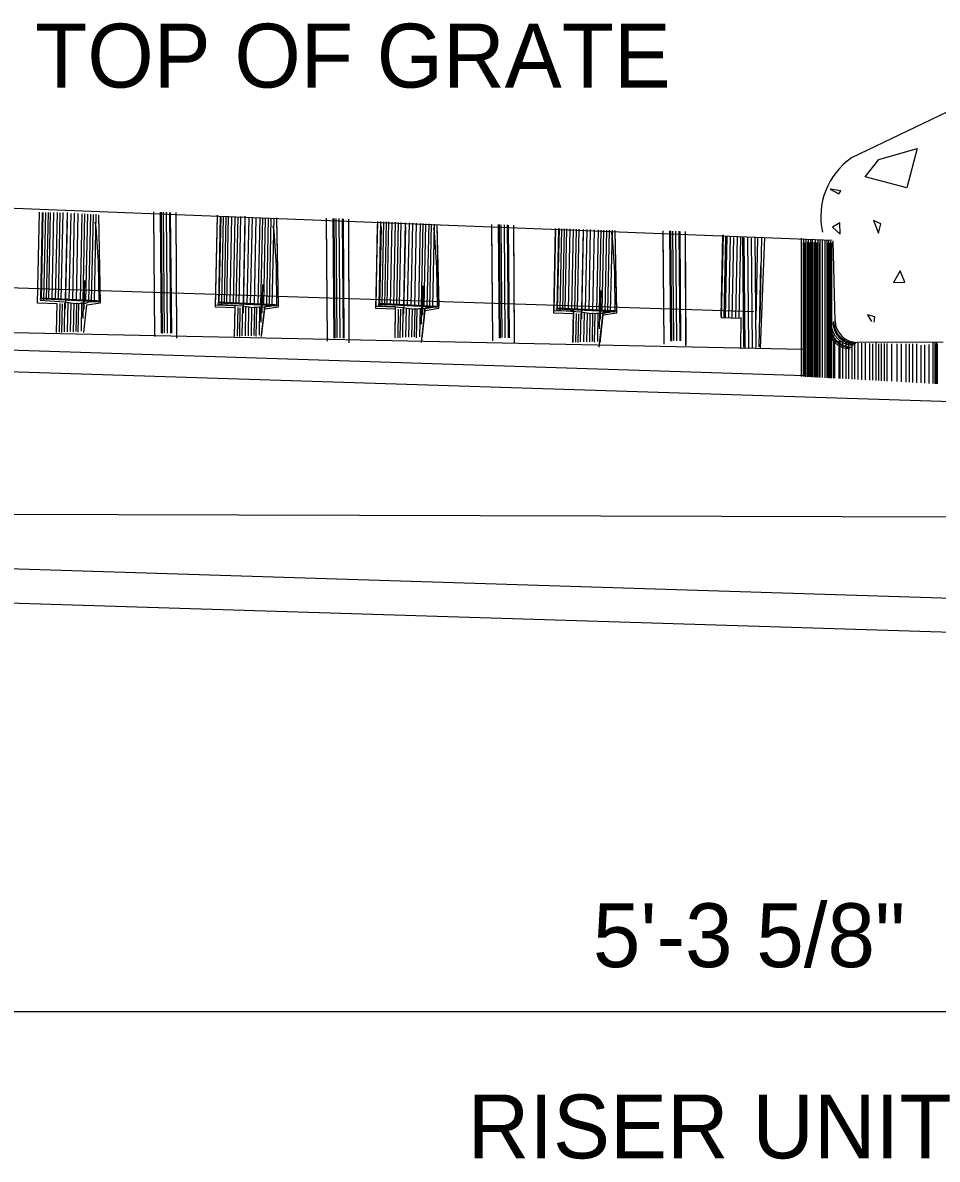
# Model space of a CAD drawing. Extents: x 4.74 to 11.91, y -5.26 to 4.54.
# Drawn here: x 6.638 to 7.498, y -0.053 to 1.015 of the extents above; entities that cross this region are included whole.
import ezdxf

# ---------------------------------------------------------------- set-up
doc = ezdxf.new("R2010")
doc.units = 0
for name, color, linetype in [('DETL-DIMS', 7, 'Continuous'), ('DETL-LINE', 7, 'Continuous'), ('DETL-NOTE', 7, 'Continuous'), ('DETL-PATT', 7, 'Continuous')]:
    doc.layers.add(name, color=color, linetype=linetype)

msp = doc.modelspace()

# ---------------------------------------------------------------- linework, layer by layer
at = {"layer": 'DETL-DIMS'}
msp.add_line((6.3455, 0.086), (8.3601, 0.086), dxfattribs=at)
at = {"layer": 'DETL-LINE'}
for p, q in [((7.6595, 1.0043), (7.4172, 0.8884)), ((6.3174, 0.8531), (7.399, 0.8109)), ((6.6522, 0.7518), (6.654, 0.8374)), ((6.6553, 0.7552), (6.657, 0.8371)), ((6.6559, 0.7552), (6.6576, 0.8371)), ((6.6582, 0.755), (6.6599, 0.8369)), ((6.6607, 0.755), (6.6624, 0.8369)), ((6.6628, 0.7552), (6.6645, 0.8371)), ((6.666, 0.755), (6.6677, 0.8369)), ((6.6692, 0.755), (6.6709, 0.8369)), ((6.6718, 0.7547), (6.6735, 0.8366)), ((6.6745, 0.755), (6.6762, 0.8369)), ((6.6785, 0.7552), (6.6803, 0.8371)), ((6.6821, 0.754), (6.6838, 0.8359)), ((6.6853, 0.7543), (6.687, 0.8362)), ((6.6888, 0.754), (6.6905, 0.8359)), ((6.6925, 0.7538), (6.6942, 0.8357)), ((6.695, 0.7538), (6.6967, 0.8357)), ((6.6977, 0.7536), (6.6994, 0.8355)), ((6.7005, 0.7534), (6.7022, 0.8353)), ((6.703, 0.7532), (6.7047, 0.8352)), ((6.7057, 0.7534), (6.7074, 0.8353)), ((6.7115, 0.7521), (6.7098, 0.8347)), ((6.7626, 0.7205), (6.7616, 0.8376)), ((6.7626, 0.7205), (6.7616, 0.8367)), ((6.7688, 0.7234), (6.7678, 0.8374)), ((6.7692, 0.7234), (6.7682, 0.8374)), ((6.7697, 0.7232), (6.7687, 0.8374)), ((6.7715, 0.7238), (6.7705, 0.8373)), ((6.7744, 0.7236), (6.7734, 0.8372)), ((6.7774, 0.7234), (6.7764, 0.8371)), ((6.7783, 0.7234), (6.7773, 0.837)), ((6.783, 0.719), (6.7824, 0.8369)), ((6.783, 0.719), (6.7824, 0.8359)), ((6.8194, 0.748), (6.8212, 0.8336)), ((6.8195, 0.7499), (6.8212, 0.8343)), ((6.8225, 0.7515), (6.8242, 0.8334)), ((6.823, 0.7515), (6.8247, 0.8334)), ((6.83, 0.7515), (6.8317, 0.8334)), ((6.8457, 0.7515), (6.8474, 0.8334)), ((6.6785, 0.7465), (6.6803, 0.8284)), ((6.7074, 0.8233), (6.7065, 0.8279)), ((6.7095, 0.7903), (6.7074, 0.8233)), ((6.8253, 0.7512), (6.827, 0.8332)), ((6.8278, 0.7512), (6.8295, 0.8332)), ((6.8331, 0.7512), (6.8348, 0.8332)), ((6.8363, 0.7512), (6.838, 0.8332)), ((6.839, 0.7509), (6.8407, 0.8328)), ((6.8417, 0.7512), (6.8434, 0.8332)), ((6.8457, 0.7428), (6.8474, 0.8247)), ((6.8492, 0.7502), (6.851, 0.8321)), ((6.8525, 0.7505), (6.8542, 0.8325)), ((6.856, 0.7502), (6.8577, 0.8321)), ((6.8597, 0.75), (6.8614, 0.832)), ((6.8622, 0.75), (6.8639, 0.832)), ((6.8648, 0.7498), (6.8665, 0.8317)), ((6.8677, 0.7497), (6.8694, 0.8316)), ((6.8702, 0.7495), (6.8719, 0.8314)), ((6.8728, 0.7497), (6.8745, 0.8316)), ((6.8746, 0.8195), (6.8737, 0.8242)), ((6.8787, 0.7502), (6.877, 0.8321)), ((6.8786, 0.7484), (6.877, 0.831)), ((6.9248, 0.716), (6.9238, 0.8316)), ((6.9248, 0.716), (6.9238, 0.8316)), ((6.9248, 0.716), (6.9239, 0.8302)), ((6.931, 0.719), (6.9301, 0.8314)), ((6.9314, 0.719), (6.9305, 0.8314)), ((6.932, 0.7188), (6.931, 0.8313)), ((6.9337, 0.7193), (6.9328, 0.8313)), ((6.9366, 0.7191), (6.9357, 0.8312)), ((6.9397, 0.719), (6.9387, 0.831)), ((6.9405, 0.719), (6.9396, 0.831)), ((6.9452, 0.7145), (6.9447, 0.8308)), ((6.9452, 0.7145), (6.9447, 0.8308)), ((6.9452, 0.7191), (6.9447, 0.8293)), ((6.9702, 0.7466), (6.9719, 0.8286)), ((6.9703, 0.749), (6.9718, 0.8258)), ((6.9703, 0.7485), (6.9718, 0.8239)), ((6.9733, 0.75), (6.9749, 0.8285)), ((6.9738, 0.75), (6.9754, 0.8239)), ((6.9761, 0.7498), (6.9777, 0.8283)), ((6.9786, 0.7498), (6.9802, 0.8282)), ((6.9807, 0.75), (6.9824, 0.8281)), ((6.9839, 0.7498), (6.9855, 0.828)), ((6.9871, 0.7498), (6.9887, 0.8278)), ((6.9898, 0.7495), (6.9914, 0.8277)), ((6.9925, 0.7498), (6.994, 0.8275)), ((6.9965, 0.75), (6.9981, 0.8273)), ((6.9965, 0.7413), (6.9982, 0.8232)), ((7, 0.7488), (7.0017, 0.8272)), ((7.0032, 0.7491), (7.0048, 0.827)), ((7.0068, 0.7488), (7.0084, 0.8268)), ((7.0105, 0.7486), (7.0121, 0.8266)), ((7.013, 0.7486), (7.0146, 0.8265)), ((7.0156, 0.7484), (7.0172, 0.8264)), ((7.0185, 0.7482), (7.0201, 0.8262)), ((7.021, 0.7481), (7.0226, 0.8261)), ((7.0236, 0.7482), (7.0252, 0.826)), ((7.0254, 0.8181), (7.0245, 0.8227)), ((7.0294, 0.747), (7.0278, 0.8258)), ((7.0295, 0.7493), (7.0279, 0.8258)), ((7.0295, 0.7488), (7.0279, 0.8258)), ((7.08, 0.7162), (7.0791, 0.8258)), ((7.08, 0.7162), (7.0791, 0.8258)), ((7.08, 0.7162), (7.0791, 0.8258)), ((7.08, 0.7162), (7.0791, 0.8239)), ((7.0862, 0.7191), (7.0853, 0.8256)), ((7.0866, 0.7191), (7.0857, 0.8256)), ((7.0872, 0.7189), (7.0862, 0.8256)), ((7.089, 0.7195), (7.088, 0.8255)), ((7.0918, 0.7193), (7.0909, 0.8254)), ((7.0949, 0.7191), (7.094, 0.8253)), ((7.0957, 0.7191), (7.0948, 0.8252)), ((7.1004, 0.7193), (7.0999, 0.825)), ((7.1005, 0.7147), (7.0999, 0.825)), ((7.1005, 0.7147), (7.0999, 0.825)), ((7.1005, 0.7157), (7.0999, 0.823)), ((6.8767, 0.7866), (6.8746, 0.8195)), ((7.0275, 0.7852), (7.0254, 0.8181)), ((7.1374, 0.7423), (7.1391, 0.822)), ((7.139, 0.822), (7.1375, 0.7446)), ((7.1405, 0.7457), (7.1421, 0.8218)), ((7.141, 0.7457), (7.1426, 0.8218)), ((7.1433, 0.7455), (7.1449, 0.8217)), ((7.1458, 0.7455), (7.1474, 0.8217)), ((7.148, 0.7457), (7.1495, 0.8216)), ((7.1511, 0.7455), (7.1527, 0.8215)), ((7.1543, 0.7455), (7.1559, 0.8214)), ((7.157, 0.7452), (7.1586, 0.8213)), ((7.1597, 0.7455), (7.1612, 0.8212)), ((7.1637, 0.7457), (7.1652, 0.8211)), ((7.1637, 0.737), (7.1654, 0.8189)), ((7.1673, 0.7445), (7.1688, 0.821)), ((7.1705, 0.7448), (7.172, 0.8209)), ((7.174, 0.7445), (7.1756, 0.8207)), ((7.1777, 0.7443), (7.1793, 0.8206)), ((7.1802, 0.7443), (7.1818, 0.8205)), ((7.1828, 0.7441), (7.1844, 0.8205)), ((7.1857, 0.7439), (7.1872, 0.8204)), ((7.1882, 0.7438), (7.1898, 0.8203)), ((7.1908, 0.7439), (7.1924, 0.8202)), ((7.1926, 0.8138), (7.1917, 0.8184)), ((7.1947, 0.7808), (7.1926, 0.8138)), ((7.1966, 0.7426), (7.195, 0.8201)), ((7.1967, 0.745), (7.1951, 0.8201)), ((7.1967, 0.7445), (7.1951, 0.8201)), ((7.1967, 0.7453), (7.1952, 0.8191)), ((7.2412, 0.7133), (7.2402, 0.8198)), ((7.2412, 0.7133), (7.2403, 0.8198)), ((7.2412, 0.7133), (7.2403, 0.8198)), ((7.2412, 0.7133), (7.2403, 0.8198)), ((7.2412, 0.7133), (7.2403, 0.8173)), ((7.2474, 0.7162), (7.2465, 0.8196)), ((7.2478, 0.7162), (7.2469, 0.8196)), ((7.2483, 0.716), (7.2474, 0.8196)), ((7.2501, 0.7166), (7.2492, 0.8195)), ((7.253, 0.7164), (7.2521, 0.8194)), ((7.256, 0.7162), (7.2552, 0.8193)), ((7.2569, 0.7162), (7.256, 0.8192)), ((7.2616, 0.7164), (7.261, 0.8191)), ((7.2616, 0.7129), (7.2611, 0.8191)), ((7.2616, 0.7118), (7.2611, 0.8191)), ((7.2616, 0.7118), (7.2611, 0.8191)), ((7.2617, 0.7129), (7.2611, 0.8165)), ((7.2945, 0.7391), (7.2961, 0.8155)), ((7.2964, 0.8161), (7.2948, 0.7382)), ((7.2975, 0.7386), (7.2991, 0.8147)), ((7.2987, 0.7386), (7.3003, 0.8147)), ((7.302, 0.738), (7.3035, 0.8141)), ((7.3049, 0.7375), (7.3065, 0.8135)), ((7.3084, 0.7378), (7.31, 0.8138)), ((7.3116, 0.7375), (7.3132, 0.8135)), ((7.3159, 0.7104), (7.315, 0.8134)), ((7.3171, 0.7101), (7.3162, 0.8131)), ((7.3206, 0.7101), (7.3197, 0.8131)), ((7.3241, 0.7098), (7.3232, 0.8128)), ((7.3274, 0.7101), (7.3265, 0.8131)), ((7.3275, 0.7368), (7.3291, 0.8129)), ((7.3313, 0.7372), (7.3329, 0.8132)), ((7.3316, 0.7093), (7.3357, 0.8135)), ((7.3703, 0.6829), (7.3703, 0.8129)), ((7.372, 0.6828), (7.372, 0.8087)), ((7.3724, 0.6827), (7.3724, 0.8114)), ((7.3724, 0.6827), (7.3724, 0.8087)), ((7.3727, 0.6827), (7.3727, 0.8087)), ((7.3729, 0.6827), (7.3729, 0.8087)), ((7.3731, 0.6827), (7.3731, 0.8087)), ((7.3741, 0.6827), (7.3741, 0.8085)), ((7.3745, 0.6826), (7.3745, 0.8116)), ((7.376, 0.6825), (7.376, 0.8093)), ((7.3767, 0.6825), (7.3767, 0.8114)), ((7.3781, 0.6825), (7.3781, 0.8087)), ((7.379, 0.6824), (7.379, 0.8114)), ((7.3802, 0.6823), (7.3802, 0.809)), ((7.3805, 0.6823), (7.3805, 0.8114)), ((7.3821, 0.6822), (7.3821, 0.809)), ((7.3833, 0.6822), (7.3833, 0.8114)), ((7.3845, 0.6821), (7.3845, 0.8087)), ((7.3857, 0.682), (7.3857, 0.8114)), ((7.3859, 0.682), (7.3859, 0.8085)), ((7.3873, 0.682), (7.3873, 0.8085)), ((7.3878, 0.6819), (7.3878, 0.8111)), ((7.39, 0.6818), (7.39, 0.8107)), ((7.39, 0.6818), (7.39, 0.8087)), ((7.3923, 0.6817), (7.3923, 0.8104)), ((7.3923, 0.6817), (7.3923, 0.8085)), ((7.3942, 0.6816), (7.3942, 0.8104)), ((7.3945, 0.6815), (7.3945, 0.8085)), ((7.3959, 0.6815), (7.3959, 0.8102)), ((7.397, 0.6814), (7.397, 0.8085)), ((7.3977, 0.6814), (7.3977, 0.81)), ((7.3985, 0.6813), (7.3985, 0.8083)), ((7.4017, 0.7352), (7.4, 0.8099)), ((6.71, 0.7533), (6.7095, 0.7903)), ((6.8772, 0.7496), (6.8767, 0.7866)), ((7.028, 0.7482), (7.0275, 0.7852)), ((7.1952, 0.7438), (7.1947, 0.7808)), ((7.3304, 0.7107), (7.332, 0.7868)), ((6.372, 0.7746), (7.3255, 0.7438)), ((6.6962, 0.7461), (6.6967, 0.773)), ((6.8634, 0.7423), (6.8638, 0.7693)), ((6.6952, 0.7372), (6.6956, 0.7642)), ((6.8623, 0.7335), (6.8628, 0.7604)), ((7.0131, 0.732), (7.0136, 0.759)), ((7.0142, 0.7409), (7.0146, 0.7679)), ((7.1814, 0.7366), (7.1818, 0.7635)), ((6.6707, 0.7512), (6.6522, 0.7518)), ((6.6543, 0.756), (6.7079, 0.7533)), ((6.6546, 0.7546), (6.6775, 0.753)), ((6.655, 0.7569), (6.7086, 0.7542)), ((6.6702, 0.7243), (6.6707, 0.7512)), ((6.673, 0.7245), (6.6735, 0.7514)), ((6.6752, 0.7243), (6.6756, 0.7512)), ((6.6775, 0.753), (6.6877, 0.7514)), ((6.6775, 0.7248), (6.6779, 0.7518)), ((6.6805, 0.7248), (6.6809, 0.7518)), ((6.6833, 0.725), (6.6837, 0.752)), ((6.6861, 0.7248), (6.6866, 0.7518)), ((6.6877, 0.7514), (6.6927, 0.7519)), ((6.6886, 0.7252), (6.6891, 0.7521)), ((6.6905, 0.7245), (6.691, 0.7514)), ((6.6927, 0.7519), (6.6977, 0.7518)), ((6.6936, 0.7253), (6.694, 0.7523)), ((6.6956, 0.7241), (6.6985, 0.7502)), ((6.6977, 0.7518), (6.7014, 0.7533)), ((6.6985, 0.7502), (6.7115, 0.7521)), ((6.7014, 0.7533), (6.7079, 0.7532)), ((6.7079, 0.7532), (6.7092, 0.7533)), ((6.7092, 0.7533), (6.71, 0.7533)), ((6.8378, 0.7475), (6.8194, 0.748)), ((6.8379, 0.7493), (6.8195, 0.7499)), ((6.8214, 0.7522), (6.8751, 0.7496)), ((6.8218, 0.7508), (6.8446, 0.7492)), ((6.8221, 0.7531), (6.8758, 0.7505)), ((6.8374, 0.7205), (6.8379, 0.7493)), ((6.8446, 0.7492), (6.8549, 0.7476)), ((6.8446, 0.7211), (6.8451, 0.748)), ((6.8476, 0.7211), (6.8481, 0.748)), ((6.8505, 0.7212), (6.8509, 0.7482)), ((6.8533, 0.7211), (6.8537, 0.748)), ((6.8549, 0.7476), (6.8599, 0.7482)), ((6.8558, 0.7214), (6.8563, 0.7484)), ((6.8599, 0.7482), (6.8648, 0.748)), ((6.8607, 0.7216), (6.8612, 0.7485)), ((6.8628, 0.722), (6.8657, 0.7482)), ((6.8648, 0.748), (6.8685, 0.7496)), ((6.8657, 0.7482), (6.8787, 0.7502)), ((6.8657, 0.7464), (6.8786, 0.7484)), ((6.8685, 0.7496), (6.8751, 0.7494)), ((6.8751, 0.7494), (6.8763, 0.7496)), ((6.8763, 0.7496), (6.8772, 0.7496)), ((6.9887, 0.7484), (6.9703, 0.749)), ((6.9887, 0.7479), (6.9703, 0.7485)), ((6.9722, 0.7508), (7.0259, 0.7482)), ((6.9726, 0.7494), (6.9954, 0.7478)), ((6.9729, 0.7517), (7.0266, 0.749)), ((6.9882, 0.7191), (6.9887, 0.7484)), ((6.9882, 0.7191), (6.9887, 0.7479)), ((6.9954, 0.7478), (7.0057, 0.7462)), ((7.0156, 0.7466), (7.0193, 0.7482)), ((7.0165, 0.7473), (7.0295, 0.7493)), ((7.0165, 0.7468), (7.0295, 0.7488)), ((7.0193, 0.7482), (7.0259, 0.748)), ((7.0259, 0.748), (7.0271, 0.7482)), ((7.0271, 0.7482), (7.028, 0.7482)), ((7.1803, 0.7277), (7.1808, 0.7547)), ((6.8374, 0.7205), (6.8378, 0.7475)), ((6.8402, 0.7207), (6.8407, 0.7477)), ((6.8423, 0.7205), (6.8428, 0.7475)), ((6.8577, 0.7207), (6.8582, 0.7477)), ((6.8628, 0.7204), (6.8657, 0.7464)), ((6.9886, 0.7461), (6.9702, 0.7466)), ((6.9882, 0.7191), (6.9886, 0.7461)), ((6.991, 0.7193), (6.9915, 0.7462)), ((6.9931, 0.7191), (6.9936, 0.7461)), ((6.9954, 0.7197), (6.9959, 0.7466)), ((6.9984, 0.7197), (6.9989, 0.7466)), ((7.0012, 0.7198), (7.0017, 0.7468)), ((7.0041, 0.7197), (7.0045, 0.7466)), ((7.0057, 0.7462), (7.0107, 0.7468)), ((7.0066, 0.72), (7.007, 0.747)), ((7.0085, 0.7193), (7.009, 0.7462)), ((7.0107, 0.7468), (7.0156, 0.7466)), ((7.0115, 0.7202), (7.012, 0.7471)), ((7.0129, 0.7148), (7.0165, 0.7473)), ((7.0136, 0.7206), (7.0165, 0.7468)), ((7.0136, 0.719), (7.0165, 0.745)), ((7.0165, 0.745), (7.0294, 0.747)), ((7.1558, 0.7418), (7.1374, 0.7423)), ((7.1375, 0.745), (7.1559, 0.7445)), ((7.1559, 0.7441), (7.1375, 0.7446)), ((7.1394, 0.7465), (7.1931, 0.7438)), ((7.1398, 0.7451), (7.1626, 0.7435)), ((7.1401, 0.7474), (7.1938, 0.7447)), ((7.1559, 0.7445), (7.1554, 0.7148)), ((7.1554, 0.7148), (7.1559, 0.7436)), ((7.1554, 0.7148), (7.1558, 0.7418)), ((7.1582, 0.715), (7.1587, 0.7419)), ((7.1603, 0.7148), (7.1608, 0.7418)), ((7.1626, 0.7435), (7.1729, 0.7419)), ((7.1626, 0.7153), (7.1631, 0.7423)), ((7.1656, 0.7153), (7.1661, 0.7423)), ((7.1685, 0.7155), (7.1689, 0.7425)), ((7.1713, 0.7153), (7.1717, 0.7423)), ((7.1729, 0.7419), (7.1779, 0.7424)), ((7.1738, 0.7157), (7.1742, 0.7426)), ((7.1757, 0.715), (7.1762, 0.7419)), ((7.1779, 0.7424), (7.1828, 0.7422)), ((7.1787, 0.7158), (7.1792, 0.7428)), ((7.1801, 0.7109), (7.1837, 0.7434)), ((7.1801, 0.7105), (7.1837, 0.743)), ((7.1808, 0.7163), (7.1837, 0.7425)), ((7.1808, 0.7146), (7.1837, 0.7407)), ((7.1828, 0.7422), (7.1865, 0.7438)), ((7.1837, 0.7434), (7.1967, 0.7453)), ((7.1837, 0.743), (7.1967, 0.745)), ((7.1837, 0.7425), (7.1967, 0.7445)), ((7.1837, 0.7407), (7.1966, 0.7426)), ((7.1865, 0.7438), (7.1931, 0.7437)), ((7.1931, 0.7437), (7.1943, 0.7438)), ((7.1943, 0.7438), (7.1952, 0.7438)), ((7.2948, 0.7382), (7.3132, 0.7377)), ((7.3132, 0.7382), (7.3127, 0.7089)), ((6.371, 0.7295), (7.3712, 0.7084)), ((6.3472, 0.7166), (7.3731, 0.6838)), ((7.4003, 0.7162), (7.4003, 0.6813)), ((7.4013, 0.7162), (7.4013, 0.6812)), ((7.4051, 0.7162), (7.4051, 0.681)), ((7.4063, 0.716), (7.4063, 0.6809)), ((7.4086, 0.7157), (7.4086, 0.6808)), ((7.4117, 0.7155), (7.4117, 0.6806)), ((7.4143, 0.715), (7.4143, 0.6805)), ((7.4174, 0.715), (7.4174, 0.6803)), ((7.4198, 0.7148), (7.4198, 0.6802)), ((7.5032, 0.715), (7.4225, 0.7148)), ((7.4231, 0.7143), (7.4231, 0.68)), ((7.4264, 0.7141), (7.4264, 0.6798)), ((7.43, 0.7141), (7.43, 0.6796)), ((7.4342, 0.7139), (7.4342, 0.6794)), ((7.4368, 0.7136), (7.4368, 0.6793)), ((7.4401, 0.7148), (7.4401, 0.6791)), ((7.4425, 0.7136), (7.4425, 0.679)), ((7.4449, 0.7139), (7.4449, 0.6788)), ((7.4477, 0.7139), (7.4477, 0.6787)), ((7.4503, 0.7139), (7.4503, 0.6785)), ((7.4546, 0.7136), (7.4546, 0.6783)), ((7.4596, 0.7136), (7.4596, 0.678)), ((7.4638, 0.7136), (7.4638, 0.6778)), ((7.4681, 0.7136), (7.4681, 0.6775)), ((7.4712, 0.7136), (7.4712, 0.6774)), ((7.4745, 0.7136), (7.4745, 0.6772)), ((7.4783, 0.7134), (7.4783, 0.677)), ((7.4823, 0.7122), (7.4823, 0.6768)), ((7.4856, 0.7127), (7.4856, 0.6766)), ((7.4899, 0.7129), (7.4899, 0.6764)), ((7.4935, 0.7146), (7.4935, 0.6762)), ((7.4953, 0.7146), (7.4953, 0.6761)), ((7.4958, 0.7134), (7.4958, 0.676)), ((7.497, 0.7148), (7.497, 0.676)), ((7.4977, 0.7134), (7.4977, 0.676)), ((6.353, 0.6962), (8.3577, 0.6322)), ((6.3469, 0.5541), (8.3614, 0.5488)), ((6.3527, 0.5109), (8.3631, 0.448)), ((6.3527, 0.4787), (8.3631, 0.4158))]:
    msp.add_line(p, q, dxfattribs=at)
for centre, radius, start, end in [((7.4556, 0.8331), 0.0673, 124.7817, 192.652), ((7.4159, 0.7297), 0.0208, 181.2803, 270.1418), ((7.417, 0.7309), 0.0208, 181.2803, 270.1418), ((7.418, 0.7311), 0.0208, 181.2803, 270.1418), ((7.4187, 0.7331), 0.0208, 181.2803, 270.1418), ((7.4204, 0.734), 0.0208, 181.2803, 270.1418), ((7.4211, 0.7349), 0.0208, 181.2803, 270.1418), ((7.4225, 0.7357), 0.0208, 181.2803, 270.1418)]:
    msp.add_arc(centre, radius, start, end, dxfattribs=at)
at = {"layer": 'DETL-PATT'}
for points in [[(7.4427, 0.8869), (7.4789, 0.897), (7.469, 0.8601), (7.43, 0.8705)], [(7.4051, 0.8545), (7.407, 0.8572), (7.397, 0.8588)], [(7.3993, 0.8233), (7.4065, 0.8167), (7.4061, 0.8273)], [(7.4377, 0.8295), (7.4425, 0.8175), (7.4448, 0.8262)], [(7.4567, 0.7712), (7.4672, 0.7716), (7.4629, 0.7821)]]:
    msp.add_lwpolyline(points, close=True, dxfattribs=at)
msp.add_lwpolyline([(7.4383, 0.7339), (7.439, 0.7389), (7.4323, 0.7407), (7.4358, 0.7346)], dxfattribs=at)

# ---------------------------------------------------------------- texts
at = {"layer": 'DETL-NOTE'}
for s, p in [('TOP OF GRATE', (6.65, 0.9544)), ('5\'-3 5/8"', (7.1741, 0.1277)), ('RISER UNIT', (7.0564, -0.052))]:
    msp.add_text(s, height=0.06, dxfattribs=at).set_placement(p)

doc.saveas('drawing.dxf')
